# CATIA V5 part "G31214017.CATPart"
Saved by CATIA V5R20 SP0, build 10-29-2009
Part number: G31214017
Revision: 22
Definition: design
Nomenclature: G31214017
Source: made
Description: NOT SPECIFIED
Bounding box of the stored display mesh (mm): x -6 to 17, y -12.31 to 12.31, z -12.5 to 12.5
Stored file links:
  C:\Users\Raffaele\Desktop\3D X SITO CF\BOLEX\23-BUSH REF 312\G31214017.CATPart

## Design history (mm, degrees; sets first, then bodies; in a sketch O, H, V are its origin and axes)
Body1 "MANIFOLD_SOLID_BREP #3587" (main body)
  Solid1: solid without history
Body2 "MANIFOLD_SOLID_BREP #3730"
  Solid2: solid without history
Body3 "MANIFOLD_SOLID_BREP #3873"
  Solid3: solid without history
Body4 "MANIFOLD_SOLID_BREP #4016"
  Solid4: solid without history
Body5 "MANIFOLD_SOLID_BREP #4159"
  Solid5: solid without history
Body6 "MANIFOLD_SOLID_BREP #4302"
  Solid6: solid without history
Body7 "MANIFOLD_SOLID_BREP #4445"
  Solid7: solid without history
Body8 "MANIFOLD_SOLID_BREP #4590"
  Solid8: solid without history
Body9 "MANIFOLD_SOLID_BREP #4735"
  Solid9: solid without history
Body10 "MANIFOLD_SOLID_BREP #4880"
  Solid10: solid without history
Body11 "MANIFOLD_SOLID_BREP #5025"
  Solid11: solid without history
Body12 "MANIFOLD_SOLID_BREP #5168"
  Solid12: solid without history
Body13 "MANIFOLD_SOLID_BREP #5311"
  Solid13: solid without history
Body14 "MANIFOLD_SOLID_BREP #5456"
  Solid14: solid without history
Body15 "MANIFOLD_SOLID_BREP #5601"
  Solid15: solid without history
Body16 "MANIFOLD_SOLID_BREP #5746"
  Solid16: solid without history
Body17 "MANIFOLD_SOLID_BREP #5891"
  Solid17: solid without history
Body18 "MANIFOLD_SOLID_BREP #6036"
  Solid18: solid without history
Body19 "MANIFOLD_SOLID_BREP #6181"
  Solid19: solid without history
Body20 "MANIFOLD_SOLID_BREP #6326"
  Solid20: solid without history
Body21 "MANIFOLD_SOLID_BREP #6471"
  Solid21: solid without history
Body22 "MANIFOLD_SOLID_BREP #6616"
  Solid22: solid without history
Body23 "MANIFOLD_SOLID_BREP #6761"
  Solid23: solid without history
Body24 "MANIFOLD_SOLID_BREP #6906"
  Solid24: solid without history
Body25 "MANIFOLD_SOLID_BREP #7051"
  Solid25: solid without history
